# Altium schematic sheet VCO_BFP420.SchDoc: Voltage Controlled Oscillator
size A4; Author: Alemla; Revision: 1.2; SheetNumber: 3; SheetTotal: 7; SPICEModelCacheUMHTQHEF: <root> / <DocumentId>UMHTQHEF</DocumentId> / </root>
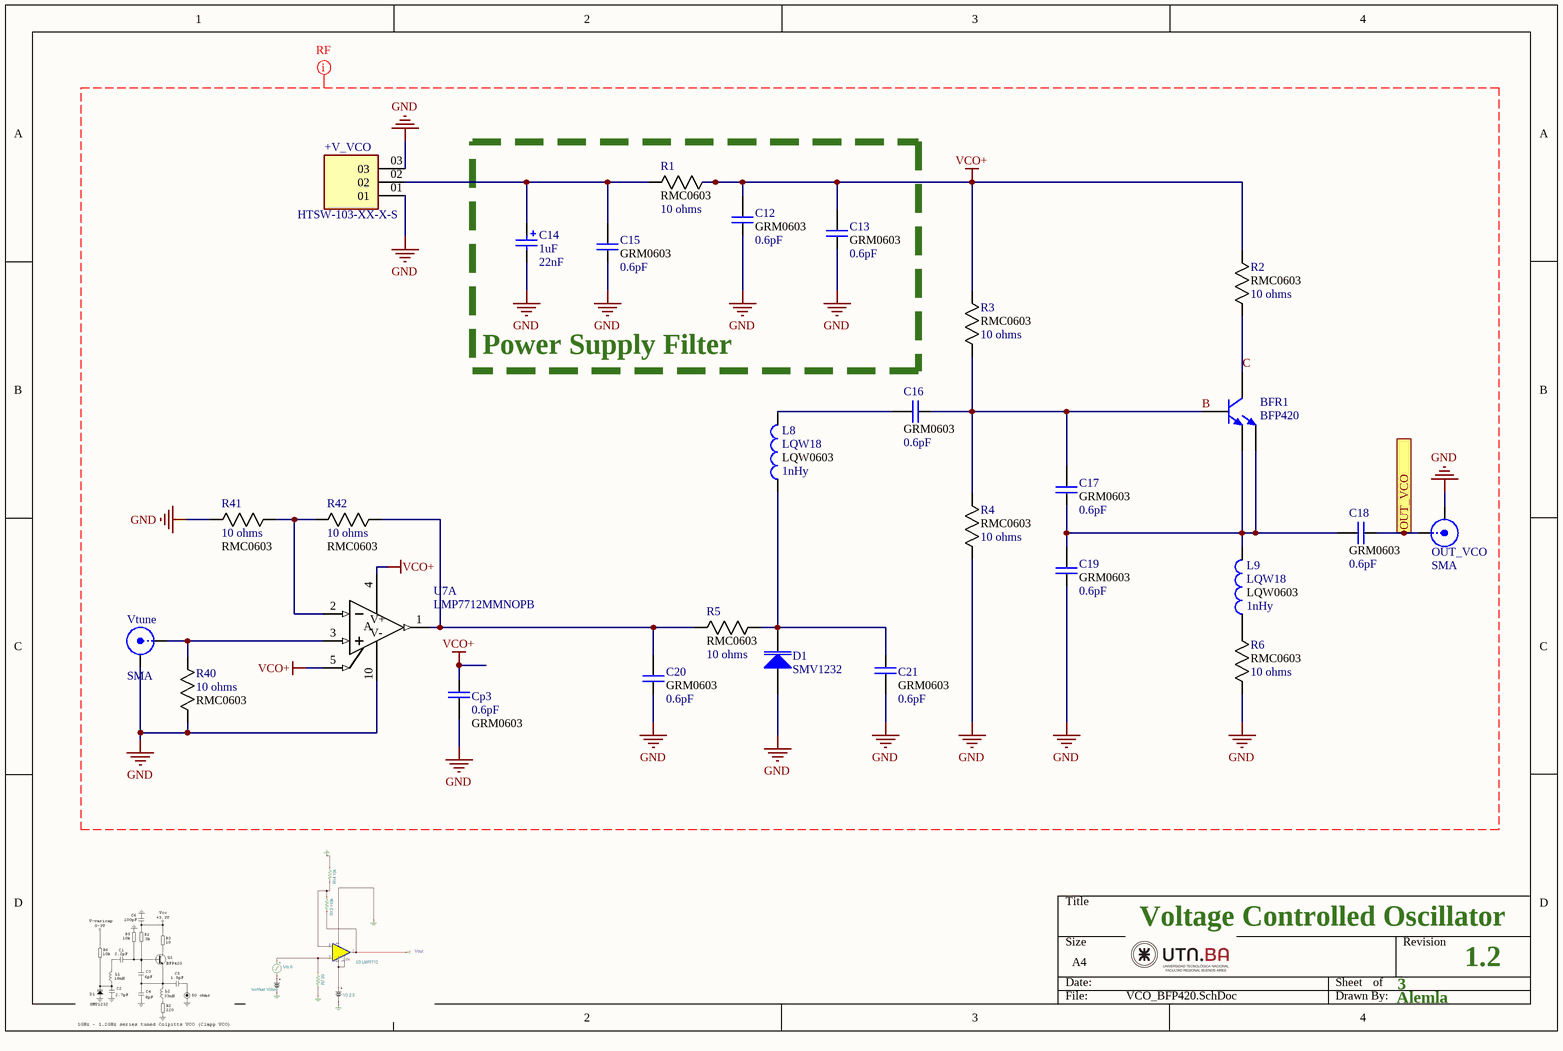
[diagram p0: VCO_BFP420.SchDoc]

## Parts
+V_VCO  HTSW-103-XX-X-S  [SAMTEC_HTSW-103-XX-X-S]
BFR1  BFP420  [SOT-343_N]
C12  value 0.6pF  footprint: GRM0603  [CAPC1608X90N]  (hidden comment: Cap 0603)
C13  value 0.6pF  footprint: GRM0603  [CAPC1608X90N]  (hidden comment: Cap 0603)
C14  1uF  value 22nF  [6-0805_N]
C15  value 0.6pF  footprint: GRM0603  [CAPC1608X90N]  (hidden comment: Cap 0603)
C16  value 0.6pF  footprint: GRM0603  [CAPC1608X90N]  (hidden comment: Cap 0603)
C17  value 0.6pF  footprint: GRM0603  [CAPC1608X90N]  (hidden comment: Cap 0603)
C18  value 0.6pF  footprint: GRM0603  [CAPC1608X90N]  (hidden comment: Cap 0603)
C19  value 0.6pF  footprint: GRM0603  [CAPC1608X90N]  (hidden comment: Cap 0603)
C20  value 0.6pF  footprint: GRM0603  [CAPC1608X90N]  (hidden comment: Cap 0603)
C21  value 0.6pF  footprint: GRM0603  [CAPC1608X90N]  (hidden comment: Cap 0603)
Cp3  value 0.6pF  footprint: GRM0603  [CAPC1608X90N]  (hidden comment: Cap 0603)
D1  SMV1232  [6-0805_N]
L8  LQW18  value 1nHy  Parameter 1: LQW0603  [INDC1608X100N]
L9  LQW18  value 1nHy  Parameter 1: LQW0603  [INDC1608X100N]
OUT_VCO  SMA  [SMA-142-0701-851_V2]
R1  value 10 ohms  footprint: RMC0603  [RESC1508X55N]  (hidden comment: Resistor)
R2  value 10 ohms  footprint: RMC0603  [RESC1508X55N]  (hidden comment: Resistor)
R3  value 10 ohms  footprint: RMC0603  [RESC1508X55N]  (hidden comment: Resistor)
R4  value 10 ohms  footprint: RMC0603  [RESC1508X55N]  (hidden comment: Resistor)
R5  value 10 ohms  footprint: RMC0603  [RESC1508X55N]  (hidden comment: Resistor)
R6  value 10 ohms  footprint: RMC0603  [RESC1508X55N]  (hidden comment: Resistor)
R40  value 10 ohms  footprint: RMC0603  [RESC1508X55N]  (hidden comment: Resistor)
R41  value 10 ohms  footprint: RMC0603  [RESC1508X55N]  (hidden comment: Resistor)
R42  value 10 ohms  footprint: RMC0603  [RESC1508X55N]  (hidden comment: Resistor)
U7  LMP7712MMNOPB  [SOP50P490X110-10N]  (part A of 2)
Vtune  SMA  [SMA-142-0701-851_V2]

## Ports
OUT_VCO (out)

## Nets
GND: +V_VCO.01 +V_VCO.03 C12.1 C13.1 C14.2 C15.1 C19.1 C20.1 C21.2 Cp3.2 D1.1(A) OUT_VCO.2(Y) R4.1 R6.1 R40.1 R41.1 U7.10(V+) Vtune.2(Y)
VCO+: C12.2 C13.2 Cp3.1 R1.2 R2.2 R3.2 U7.4(V-) U7.5(SD1)
B: BFR1.4(B) C16.1 C17.2 R3.1 R4.2
C: BFR1.2(C) R2.1
OUT_VCO: C18.1 OUT_VCO.1(X) ; port OUT_VCO
Net+V_VCO_02: +V_VCO.02 C14.1 C15.2 R1.1
NetBFR1_1: BFR1.1(E) BFR1.3(E) C17.1 C18.2 C19.2 L9.2
NetC16_2: C16.2 L8.2
NetC20_2: C20.2 R5.2 R42.2 U7.1(OUT)
NetC21_1: C21.1 D1.2(K) L8.1 R5.1
NetL9_1: L9.1 R6.2
NetR40_2: R40.2 U7.3(IN+) Vtune.1(X)
NetR41_2: R41.2 R42.1 U7.2(IN-)

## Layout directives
net class RF50R: B, C, GND, VCO+

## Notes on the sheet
- Power Supply Filter

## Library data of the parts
+V_VCO = HTSW-103-XX-X-S: Conn Unshrouded Header HDR 3 POS 2.54mm Solder ST Top Entry Thru-Hole Bag; MP: HTSW-103-08-S-S; MF: Samtec
BFR1 = BFR460: NPN Bipolar Transistor
C12 C13 C15-C21 Cp3 = Cap: Capacitor GRM18 0603
C14 = Cap Pol2_1: Polarized Capacitor (Axial)
D1 = D Varactor: Variable Capacitance Diode; Note: Pin 2 is not connected and not drawn.
L8 L9 = LQW18: Ind RF Chip Wirewound 18nH 5% 100MHz 40Q-Factor 550mA 0603 Paper T/R; MP: LQW18AN18NJ00D
OUT_VCO Vtune = SMA: SMA Straight Connector
R1-R6 R40-R42 = Resistor: Resistor RMC0603; Mfr_Name: Stackpole International
U7 = LMP7712MMNOPB: No Description Available; Mfr_Name: Texas Instruments; Manufacturer: NationalSemiconductor; Characteristics: LMP7712MM18VPrecisonDualLowNoiseCMOSInputOpAmpwithShutdown; CompType: OpAmpIC; TaMin_C: -400; TaMax_C: 1250; ComponentLink1DescBC: LMP7712Datasheet; ComponentLink2DescA4: LMP7712WebPage; ComponentLink3DescAC: MUB10APackageWebPage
